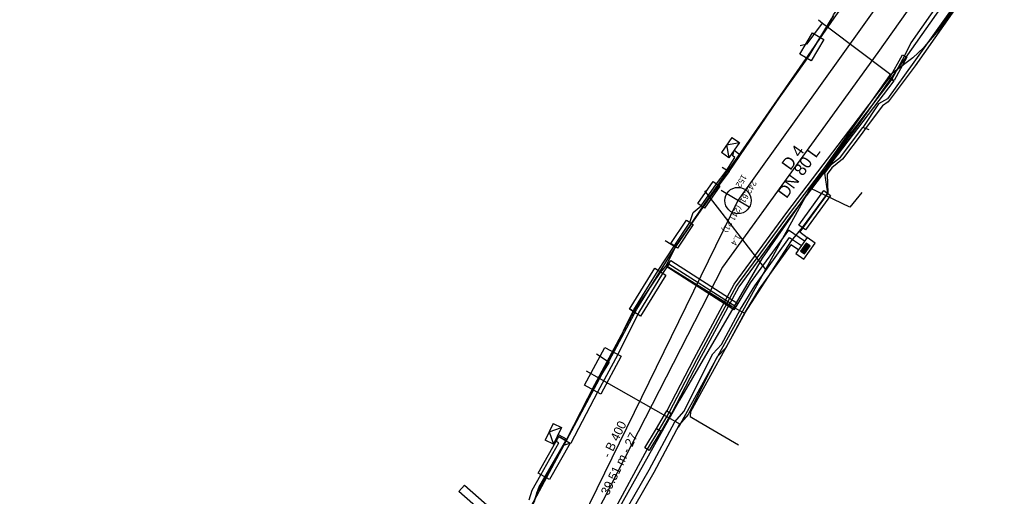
# Model space of a CAD drawing. Extents: x -600636 to -600148, y -1203980 to -1203569.
# Drawn here: x -600425.2 to -600351.2, y -1203776.3 to -1203740.1 of the extents above; entities that cross this region are included whole.
import ezdxf

# ---------------------------------------------------------------- set-up
doc = ezdxf.new("R2010")
doc.units = 0
for name, color, linetype in [('Cetin zam průběh', 7, 'Continuous'), ('EON objekty', 7, 'Continuous'), ('EON podzemní NN', 7, 'Continuous'), ('EON podzemní VN', 7, 'Continuous'), ('GasNet NTL', 7, 'Continuous'), ('Implicitní', 7, 'Continuous'), ('VaK Břeclav_kanalizace', 7, 'Continuous'), ('VaK Břeclav_kanalizace_popis', 7, 'Continuous'), ('Vak Břeclav_vodovod', 7, 'Continuous'), ('Vak Břeclav_vodovod_popis', 7, 'Continuous'), ('Vrstva 9', 7, 'Continuous')]:
    doc.layers.add(name, color=color, linetype=linetype)

# ---------------------------------------------------------------- blocks, each defined once
blk = doc.blocks.new('NN630')
at = {"layer": 'Vrstva 9'}
for points in [[(-0.003, -0.7), (-0.703, 0)], [(-0.703, -0.7), (-0.703, 0), (0.697, 0), (0.697, -0.7)], [(-0.703, -0.7), (0.697, -0.7)], [(-0.003, -0.7), (0.697, 0)]]:
    blk.add_lwpolyline(points, dxfattribs=at)
blk = doc.blocks.new('NN620')
at = {"layer": 'EON objekty'}
for points in [[(0.752, 0.004), (-0.748, 0.004)], [(-0.748, 0.004), (-0.748, -0.746)], [(0.752, -0.746), (0.752, 0.004)], [(0.368, -0.18), (-0.376, -0.18)], [(-0.376, -0.18), (-0.376, -0.558)], [(-0.376, -0.558), (0.368, -0.558)], [(0.321, -0.227), (-0.329, -0.227)], [(-0.329, -0.227), (-0.329, -0.51)], [(-0.329, -0.51), (0.321, -0.51)], [(0.274, -0.274), (-0.281, -0.274)], [(-0.281, -0.274), (-0.281, -0.463)], [(-0.281, -0.463), (0.274, -0.463)], [(0.227, -0.321), (-0.234, -0.321)], [(-0.234, -0.321), (-0.234, -0.416)], [(-0.234, -0.416), (0.227, -0.416)], [(-0.193, -0.369), (0.185, -0.369)], [(0.227, -0.416), (0.227, -0.321)], [(0.274, -0.463), (0.274, -0.274)], [(0.321, -0.51), (0.321, -0.227)], [(0.368, -0.558), (0.368, -0.18)], [(-0.748, -0.746), (0.752, -0.746)]]:
    blk.add_lwpolyline(points, dxfattribs=at)
blk = doc.blocks.new('MoSymbol 2')
at = {"layer": 'Implicitní'}
blk.add_line((0, 0.0005), (0, -0.00075), dxfattribs=at)
blk.add_circle((0, 0), 0.0005, dxfattribs=at)

msp = doc.modelspace()

# ---------------------------------------------------------------- linework, layer by layer
at = {"layer": 'Cetin zam průběh'}
for points in [[(-600448.32, -1203764.77), (-600445.41, -1203766.9), (-600434.97, -1203774.92), (-600422.32, -1203783.12), (-600413.93, -1203789.04), (-600405.18, -1203794.93), (-600400.25, -1203797.98), (-600398.96, -1203798.36), (-600397.12, -1203797.36), (-600388.96, -1203781.95), (-600378.33, -1203762.13), (-600375.93, -1203758.23), (-600373.1, -1203754.01), (-600370.24, -1203749.96), (-600363.35, -1203740.04), (-600357.38, -1203731.69), (-600349.33, -1203720.15), (-600345.8, -1203715.19), (-600340.07, -1203706.96), (-600329.02, -1203689.27)], [(-600349.98, -1203733.11), (-600352.35, -1203736.35), (-600353.65, -1203738.25), (-600357.31, -1203743.38), (-600359.31, -1203746.17), (-600359.98, -1203746.53), (-600361.18, -1203748.34)], [(-600371.33, -1203751.67), (-600367.69, -1203746.37), (-600365.25, -1203742.89), (-600363.56, -1203740.1), (-600363.39, -1203739.78), (-600362.14, -1203738.07)], [(-600365.25, -1203742.89), (-600363.56, -1203740.1)], [(-600370.13, -1203762.42), (-600366.6, -1203756.94), (-600365.75, -1203755.93), (-600363.84, -1203753.31), (-600364.05, -1203751.8), (-600363.56, -1203751.12), (-600362.86, -1203750.58), (-600361.18, -1203748.34)], [(-600360.7, -1203748.52), (-600361.18, -1203748.34)], [(-600371.33, -1203751.67), (-600371.96, -1203752.5), (-600372.95, -1203753.85), (-600374.23, -1203755.69), (-600375.4, -1203757.39)], [(-600371.85, -1203751.35), (-600371.33, -1203751.67)], [(-600372.95, -1203753.85), (-600371.96, -1203752.5)], [(-600365.75, -1203755.93), (-600363.84, -1203753.31)], [(-600375.4, -1203757.39), (-600374.23, -1203755.69)], [(-600376.17, -1203756.91), (-600375.4, -1203757.39)], [(-600376.1, -1203758.83), (-600375.4, -1203757.39)], [(-600378.52, -1203762.28), (-600376.55, -1203759.37), (-600376.1, -1203758.83)], [(-600378.52, -1203762.28), (-600376.55, -1203759.37)], [(-600371.11, -1203761.93), (-600376.1, -1203758.83)], [(-600376.1, -1203758.83), (-600371.11, -1203761.93), (-600370.13, -1203762.42)], [(-600383.64, -1203771.99), (-600381.53, -1203767.83), (-600380.04, -1203765.1), (-600378.52, -1203762.28)], [(-600378.9, -1203762.06), (-600378.52, -1203762.28)], [(-600370.13, -1203762.42), (-600374.25, -1203769.92), (-600374.28, -1203770.27), (-600373.61, -1203770.66), (-600370.61, -1203772.41)], [(-600381.53, -1203767.83), (-600380.04, -1203765.1)], [(-600384.3, -1203771.63), (-600383.64, -1203771.99)], [(-600396.69, -1203794.26), (-600395.96, -1203792.99), (-600395.05, -1203791.52), (-600394.27, -1203790.24), (-600392.18, -1203786.77), (-600391.09, -1203785.14), (-600390.52, -1203784.22), (-600388.33, -1203780.56), (-600387.91, -1203779.78), (-600386.07, -1203776.57), (-600385.86, -1203775.96), (-600385.78, -1203775.65), (-600383.64, -1203771.99)], [(-600385.78, -1203775.65), (-600383.64, -1203771.99)]]:
    msp.add_lwpolyline(points, dxfattribs=at)
at = {"layer": 'EON podzemní NN'}
for points in [[(-600353.56, -1203738.45), (-600357.2, -1203743.67), (-600359.26, -1203746.4), (-600359.69, -1203746.7), (-600360.991, -1203748.45), (-600361.23, -1203748.771), (-600362.71, -1203750.75), (-600363.52, -1203751.41), (-600363.89, -1203751.87), (-600363.84, -1203753.31), (-600365.958, -1203756.243), (-600365.403, -1203756.689)], [(-600386.496, -1203776.592), (-600386.286, -1203775.861), (-600385.614, -1203774.691), (-600384.24, -1203772.273), (-600384.41, -1203772.193), (-600384.356, -1203771.737), (-600383.679, -1203772.095), (-600381.673, -1203768.224), (-600380.134, -1203765.366), (-600378.549, -1203762.184), (-600376.72, -1203759.19), (-600375.5, -1203757.33), (-600374.31, -1203755.54), (-600374.06, -1203754.79), (-600373.45, -1203754.27), (-600372.28, -1203752.61), (-600371.56, -1203751.66), (-600370.878, -1203750.607), (-600371.042, -1203750.484), (-600370.94, -1203750.06), (-600370.5, -1203750.391), (-600368.596, -1203747.604), (-600365.393, -1203743.13), (-600364.409, -1203741.504), (-600363.365, -1203739.833)], [(-600365.605, -1203756.969), (-600366.826, -1203756.134), (-600369.718, -1203760.128), (-600370.812, -1203761.945), (-600375.9, -1203758.698), (-600376.384, -1203759.407), (-600378.208, -1203762.393), (-600379.783, -1203765.558), (-600381.32, -1203768.411), (-600383.328, -1203772.286), (-600383.91, -1203772.46), (-600385.267, -1203774.889), (-600385.915, -1203776.018), (-600386.125, -1203776.749), (-600387.914, -1203779.875), (-600388.206, -1203780.448), (-600390.566, -1203784.297), (-600391.528, -1203783.719)], [(-600382.7, -1203783.539), (-600377.4, -1203774.316), (-600375.451, -1203770.681), (-600374.755, -1203769.885), (-600372.562, -1203765.52), (-600371.908, -1203764.815), (-600370.453, -1203762.124), (-600369.384, -1203760.349), (-600366.73, -1203756.684), (-600365.831, -1203757.299)], [(-600366.057, -1203757.629), (-600366.635, -1203757.234), (-600369.05, -1203760.57), (-600370.11, -1203762.33), (-600371.58, -1203765.05), (-600372.23, -1203765.75), (-600374.42, -1203770.11), (-600375.12, -1203770.91), (-600377.05, -1203774.51), (-600382.44, -1203783.89), (-600383.8, -1203784.2), (-600384.6, -1203785.48), (-600384.21, -1203786.64), (-600384.56, -1203787.45)]]:
    msp.add_lwpolyline(points, dxfattribs=at)
for points in [[(-600364.981, -1203741.148), (-600364.126, -1203741.666), (-600365.106, -1203743.289), (-600365.963, -1203742.771)], [(-600372.527, -1203752.433), (-600372.026, -1203752.784), (-600373.192, -1203754.447), (-600373.695, -1203754.094)], [(-600364.127, -1203753.116), (-600363.619, -1203753.485), (-600365.525, -1203756.108), (-600366.029, -1203755.744)], [(-600374.56, -1203755.361), (-600374.053, -1203755.697), (-600375.24, -1203757.489), (-600375.75, -1203757.149)], [(-600370.65, -1203761.68), (-600370.962, -1203762.17), (-600376.047, -1203758.92), (-600375.737, -1203758.433)], [(-600376.972, -1203759.008), (-600376.121, -1203759.534), (-600378.048, -1203762.643), (-600378.895, -1203762.118)], [(-600380.747, -1203765.027), (-600379.515, -1203765.69), (-600381.062, -1203768.565), (-600382.295, -1203767.901)], [(-600384.26, -1203771.788), (-600383.387, -1203772.283), (-600384.959, -1203775.056), (-600385.829, -1203774.564)], [(-600391.835, -1203775.947), (-600391.413, -1203775.471), (-600388.235, -1203778.285), (-600388.656, -1203778.76)]]:
    msp.add_lwpolyline(points, close=True, dxfattribs=at)
at = {"layer": 'EON podzemní VN'}
for points in [[(-600366.95, -1203635.593), (-600366.181, -1203636.795), (-600358.381, -1203643.411), (-600344.954, -1203653.759), (-600330.827, -1203664.425), (-600321.645, -1203670.963), (-600317.713, -1203673.458), (-600315.791, -1203674.896), (-600315.293, -1203675.777), (-600315.944, -1203682.246), (-600316.226, -1203683.581), (-600322.501, -1203693.042), (-600331.079, -1203704.985), (-600348.911, -1203730.288), (-600354.208, -1203737.743), (-600361.516, -1203748.136), (-600365.138, -1203753.003), (-600368.824, -1203758.254), (-600375.091, -1203769.039), (-600381.398, -1203780.278), (-600382.49, -1203782.6), (-600383.25, -1203783.59)], [(-600351.367, -1203733.129), (-600357.517, -1203741.909), (-600357.997, -1203742.909), (-600358.977, -1203744.679), (-600366.777, -1203754.899), (-600370.767, -1203760.329), (-600373.807, -1203765.959), (-600375.887, -1203769.949), (-600376.667, -1203771.279), (-600377.557, -1203772.739), (-600383.047, -1203782.909), (-600383.307, -1203783.299)]]:
    msp.add_lwpolyline(points, dxfattribs=at)
for points in [[(-600359.152, -1203744.582), (-600358.172, -1203742.812), (-600357.822, -1203743.006), (-600358.802, -1203744.776)], [(-600359.136, -1203744.558), (-600358.818, -1203744.8), (-600366.617, -1203755.019), (-600370.597, -1203760.436), (-600373.63, -1203766.053), (-600375.709, -1203770.041), (-600376.064, -1203769.856), (-600373.983, -1203765.865), (-600370.936, -1203760.222), (-600366.937, -1203754.779)], [(-600376.059, -1203769.848), (-600375.714, -1203770.05), (-600376.494, -1203771.38), (-600376.839, -1203771.178)], [(-600376.837, -1203771.175), (-600376.496, -1203771.383), (-600377.386, -1203772.843), (-600377.727, -1203772.635)]]:
    msp.add_lwpolyline(points, close=True, dxfattribs=at)
at = {"layer": 'GasNet NTL'}
for points in [[(-600321.69, -1203692.03), (-600330.58, -1203705.33), (-600337.06, -1203714.26), (-600337.47, -1203714.88), (-600341.61, -1203721.03), (-600343.93, -1203724.48), (-600344.29, -1203725.01), (-600352.8, -1203737.19), (-600355.42, -1203740.94), (-600356.36, -1203742.04), (-600356.56, -1203742.28), (-600357.37, -1203743.06), (-600358.82, -1203744.14), (-600359.04, -1203744.31), (-600359.16, -1203744.4), (-600365.08, -1203752.77), (-600365.18, -1203752.95), (-600368.57, -1203759.1), (-600375.05, -1203770.85), (-600375.18, -1203771.08)], [(-600365.94, -1203742.11), (-600365.4, -1203741.98), (-600364.23, -1203740.42)], [(-600364.55, -1203740.18), (-600364.23, -1203740.42)], [(-600364.23, -1203740.42), (-600363.75, -1203740.78), (-600359.35, -1203744.08), (-600359.04, -1203744.31)], [(-600373.19, -1203753.14), (-600368.57, -1203759.1)], [(-600361.26, -1203753.26), (-600362.16, -1203754.39), (-600365.18, -1203752.95)], [(-600381.38, -1203765.52), (-600380.42, -1203766.15), (-600381.2, -1203767.36)], [(-600382.18, -1203766.8), (-600381.2, -1203767.36)], [(-600381.2, -1203767.36), (-600381.01, -1203767.47), (-600375.79, -1203770.42), (-600375.05, -1203770.85)]]:
    msp.add_lwpolyline(points, dxfattribs=at)
at = {"layer": 'VaK Břeclav_kanalizace'}
for p, q in [((-600337.248, -1203707.145), (-600370.65, -1203753.88)), ((-600370.65, -1203753.88), (-600388.037, -1203789.358))]:
    msp.add_line(p, q, dxfattribs=at)
at = {"layer": 'Vak Břeclav_vodovod'}
msp.add_lwpolyline([(-600330.382, -1203700.926), (-600340.064, -1203714.494), (-600360.044, -1203742.638), (-600371.815, -1203758.94), (-600385.686, -1203786.009), (-600395.742, -1203804.116)], dxfattribs=at)

# ---------------------------------------------------------------- block references
at = {"layer": 'EON podzemní NN'}
for name, p, rotation in [('NN630', (-600370.94, -1203750.06), -124.38137510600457), ('NN620', (-600365.83, -1203757.3), 55.011149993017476), ('NN630', (-600384.36, -1203771.74), -115.42863054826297)]:
    msp.add_blockref(name, p, dxfattribs=dict(at, rotation=rotation))
at = {"layer": 'VaK Břeclav_kanalizace', "xscale": 1999.7500312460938, "yscale": 1999.7500312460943, "rotation": -120.83113433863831}
msp.add_blockref('MoSymbol 2', (-600370.65, -1203753.88), dxfattribs=at)

# ---------------------------------------------------------------- texts
at = {"layer": 'VaK Břeclav_kanalizace_popis'}
for s, height, rotation, p in [('152', 0.4549, 239.16887, (-600370.334, -1203751.85)), ('242,61  (241,21)', 0.45494, 239.16887, (-600369.586, -1203752.31)), ('1.4', 0.4549, 239.16887, (-600370.774, -1203756.4)), ('- B 400', 0.6824, 63.89153, (-600380.387, -1203773.467)), ('39.51 m - 27', 0.68241, 63.89153, (-600380.49, -1203776.308))]:
    msp.add_text(s, height=height, rotation=rotation, dxfattribs=at).set_placement(p)
at = {"layer": 'Vak Břeclav_vodovod_popis'}
for s, p in [('D 4', (-600366.674, -1203751.644)), ('DN 80 L', (-600366.964, -1203753.776))]:
    msp.add_text(s, height=0.9099, rotation=54.16851, dxfattribs=at).set_placement(p)

doc.saveas('drawing.dxf')
